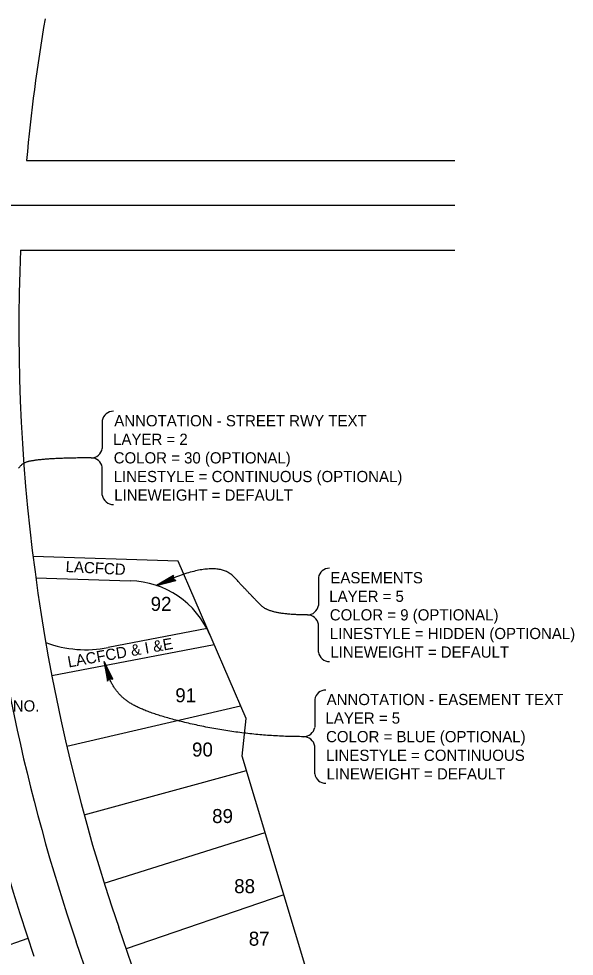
# Model space of a CAD drawing. Extents: x 6387474 to 6390971, y 1972046 to 1973920.
# Drawn here: x 6389581 to 6389978, y 1973251 to 1973920 of the extents above; entities that cross this region are included whole.
import ezdxf

# ---------------------------------------------------------------- set-up
doc = ezdxf.new("R2010")
doc.units = 0
for name, color, linetype in [('1', 7, 'Continuous'), ('2', 7, 'Continuous'), ('3', 7, 'Continuous'), ('4', 7, 'Continuous'), ('5', 7, 'Continuous'), ('7', 7, 'Continuous'), ('8', 7, 'Continuous')]:
    doc.layers.add(name, color=color, linetype=linetype)

msp = doc.modelspace()

# ---------------------------------------------------------------- linework, layer by layer
at = {"layer": '1'}
for p, q in [((6389694.9, 1973533.17), (6389591.38, 1973536.42)), ((6389743.44, 1973420.87), (6389694.9, 1973533.17)), ((6389740.69, 1973394.07), (6389743.44, 1973420.87)), ((6389875.29, 1972944.72), (6389740.69, 1973394.07))]:
    msp.add_line(p, q, dxfattribs=at)
at = {"layer": '2'}
for p, q in [((6389236.57, 1973787.32), (6389892.25, 1973787.32)), ((6389702.59, 1973027.14), (6389622.23, 1973261.52))]:
    msp.add_line(p, q, dxfattribs=at)
msp.add_arc((6390899.27, 1973699.34), 1350, 170.57423, 198.92361, dxfattribs=at)
at = {"layer": '3'}
for p, q in [((6389604.77, 1973451.56), (6389720.59, 1973473.72)), ((6389615.45, 1973401.12), (6389739.52, 1973429.94)), ((6389627.85, 1973352.05), (6389743.79, 1973383.72)), ((6389642.2, 1973303.23), (6389757.06, 1973339.42)), ((6389770.39, 1973294.92), (6389657.84, 1973256.33)), ((6389587.7, 1973263.79), (6389480.83, 1973227.16))]:
    msp.add_line(p, q, dxfattribs=at)
at = {"layer": '4'}
for p, q in [((6389586.74, 1973819.32), (6389892.25, 1973819.32)), ((6389582.46, 1973755.32), (6389892.25, 1973755.32)), ((6389732.86, 1973037.51), (6389652.51, 1973271.9))]:
    msp.add_line(p, q, dxfattribs=at)
for radius, start, end in [(1318, 170.34322, 174.77704), (1382, 177.67854, 198.92361), (1318, 177.56575, 198.92361)]:
    msp.add_arc((6390899.27, 1973699.34), radius, start, end, dxfattribs=at)
at = {"layer": '5'}
for p, q in [((6389593.34, 1973521.35), (6389660.87, 1973519.22)), ((6389715.71, 1973485.01), (6389644.98, 1973471.48))]:
    msp.add_line(p, q, dxfattribs=at)
for centre, radius, start, end in [((6389658.86, 1973455.26), 64, 23.37409, 88.19889), ((6389629.19, 1973553.98), 84, 250.04716, 280.83)]:
    msp.add_arc(centre, radius, start, end, dxfattribs=at)
at = {"layer": '8'}
for p, q in [((6389640.81, 1973633.56), (6389640.81, 1973613.58)), ((6389640.81, 1973580.27), (6389640.81, 1973600.25)), ((6389691.71, 1973523.05), (6389679.56, 1973515.82)), ((6389679.56, 1973515.82), (6389693.25, 1973519.36)), ((6389795.01, 1973521.48), (6389795.01, 1973501.5)), ((6389795.01, 1973468.19), (6389795.01, 1973488.17)), ((6389648.35, 1973448.85), (6389642.16, 1973461.57)), ((6389642.16, 1973461.57), (6389644.54, 1973447.63)), ((6389792.34, 1973434.55), (6389792.34, 1973414.57)), ((6389792.34, 1973381.26), (6389792.34, 1973401.24))]:
    msp.add_line(p, q, dxfattribs=at)
for points in [[(6389632.92, 1973606.91), (6389631.63, 1973606.91), (6389630.37, 1973606.91), (6389629.11, 1973606.9), (6389627.88, 1973606.9), (6389626.66, 1973606.89), (6389625.45, 1973606.88), (6389624.27, 1973606.86), (6389623.1, 1973606.85), (6389621.94, 1973606.83), (6389620.81, 1973606.81), (6389619.68, 1973606.79), (6389618.58, 1973606.77), (6389617.49, 1973606.75), (6389616.42, 1973606.72), (6389615.37, 1973606.69), (6389614.33, 1973606.66), (6389613.31, 1973606.63), (6389612.3, 1973606.6), (6389611.32, 1973606.56), (6389610.35, 1973606.52), (6389609.39, 1973606.48), (6389608.45, 1973606.44), (6389607.53, 1973606.4), (6389606.63, 1973606.35), (6389605.74, 1973606.3), (6389604.86, 1973606.25), (6389604.01, 1973606.2), (6389603.17, 1973606.15), (6389602.35, 1973606.09), (6389601.54, 1973606.04), (6389600.75, 1973605.98), (6389599.98, 1973605.92), (6389599.22, 1973605.85), (6389598.48, 1973605.79), (6389597.76, 1973605.72), (6389597.05, 1973605.65), (6389596.36, 1973605.58), (6389595.69, 1973605.51), (6389595.03, 1973605.43), (6389594.39, 1973605.36), (6389593.77, 1973605.28), (6389593.16, 1973605.2), (6389592.57, 1973605.12), (6389592, 1973605.03), (6389591.44, 1973604.94), (6389590.9, 1973604.86), (6389590.37, 1973604.77), (6389589.87, 1973604.67), (6389589.38, 1973604.58), (6389588.9, 1973604.48), (6389588.44, 1973604.38), (6389588, 1973604.28), (6389587.58, 1973604.18), (6389587.16, 1973604.07), (6389586.76, 1973603.95), (6389586.36, 1973603.81), (6389585.97, 1973603.65), (6389585.59, 1973603.48), (6389585.22, 1973603.3), (6389584.85, 1973603.1), (6389584.49, 1973602.89), (6389584.14, 1973602.66), (6389583.8, 1973602.41), (6389583.47, 1973602.16), (6389583.14, 1973601.88), (6389582.82, 1973601.6), (6389582.51, 1973601.29), (6389582.21, 1973600.98), (6389581.91, 1973600.64), (6389581.63, 1973600.3), (6389581.35, 1973599.94), (6389581.08, 1973599.56)], [(6389737.66, 1973518.77), (6389737.19, 1973519.28), (6389736.71, 1973519.79), (6389736.23, 1973520.3), (6389735.75, 1973520.83), (6389735.26, 1973521.35), (6389734.77, 1973521.88), (6389734.26, 1973522.41), (6389733.74, 1973522.91), (6389733.19, 1973523.38), (6389732.62, 1973523.83), (6389732.04, 1973524.25), (6389731.43, 1973524.65), (6389730.8, 1973525.03), (6389730.15, 1973525.38), (6389729.48, 1973525.71), (6389728.79, 1973526.01), (6389728.08, 1973526.29), (6389727.34, 1973526.54), (6389726.59, 1973526.77), (6389725.82, 1973526.97), (6389725.02, 1973527.15), (6389724.21, 1973527.31), (6389723.37, 1973527.44), (6389722.52, 1973527.55), (6389721.64, 1973527.63), (6389720.74, 1973527.68), (6389719.82, 1973527.72), (6389718.89, 1973527.73), (6389717.93, 1973527.71), (6389716.95, 1973527.67), (6389715.95, 1973527.6), (6389714.92, 1973527.51), (6389713.88, 1973527.4), (6389712.82, 1973527.26), (6389711.74, 1973527.09), (6389710.63, 1973526.91), (6389709.51, 1973526.69), (6389708.37, 1973526.46), (6389707.2, 1973526.2), (6389706.01, 1973525.91), (6389704.81, 1973525.6), (6389703.58, 1973525.26), (6389702.33, 1973524.9), (6389701.06, 1973524.52), (6389699.77, 1973524.11), (6389698.46, 1973523.68), (6389697.13, 1973523.22), (6389695.78, 1973522.74), (6389694.41, 1973522.23), (6389693.02, 1973521.7), (6389691.61, 1973521.14), (6389690.17, 1973520.56), (6389688.72, 1973519.96), (6389687.24, 1973519.33), (6389685.75, 1973518.67), (6389684.23, 1973517.99), (6389682.69, 1973517.29), (6389681.14, 1973516.56), (6389679.56, 1973515.81)], [(6389787.13, 1973494.83), (6389786.15, 1973494.83), (6389785.18, 1973494.84), (6389784.23, 1973494.85), (6389783.3, 1973494.87), (6389782.37, 1973494.89), (6389781.47, 1973494.91), (6389780.57, 1973494.94), (6389779.69, 1973494.98), (6389778.82, 1973495.02), (6389777.97, 1973495.06), (6389777.13, 1973495.11), (6389776.3, 1973495.16), (6389775.49, 1973495.22), (6389774.7, 1973495.28), (6389773.91, 1973495.35), (6389773.14, 1973495.42), (6389772.39, 1973495.49), (6389771.64, 1973495.57), (6389770.92, 1973495.66), (6389770.2, 1973495.75), (6389769.5, 1973495.84), (6389768.82, 1973495.94), (6389768.14, 1973496.04), (6389767.49, 1973496.15), (6389766.84, 1973496.26), (6389766.21, 1973496.38), (6389765.59, 1973496.5), (6389764.99, 1973496.63), (6389764.4, 1973496.76), (6389763.83, 1973496.89), (6389763.27, 1973497.03), (6389762.72, 1973497.18), (6389762.19, 1973497.33), (6389761.67, 1973497.48), (6389761.16, 1973497.64), (6389760.67, 1973497.8), (6389760.19, 1973497.97), (6389759.73, 1973498.14), (6389759.28, 1973498.32), (6389758.85, 1973498.5), (6389758.42, 1973498.68), (6389758.02, 1973498.87), (6389757.62, 1973499.07), (6389757.24, 1973499.27), (6389756.88, 1973499.47), (6389756.53, 1973499.68), (6389756.19, 1973499.89), (6389755.86, 1973500.11), (6389755.55, 1973500.33), (6389755.26, 1973500.56), (6389754.97, 1973500.79), (6389754.71, 1973501.03), (6389754.45, 1973501.27), (6389754.2, 1973501.51), (6389753.95, 1973501.76), (6389753.69, 1973502.02), (6389753.42, 1973502.28), (6389753.16, 1973502.55), (6389752.88, 1973502.82), (6389752.6, 1973503.1), (6389752.32, 1973503.39), (6389752.03, 1973503.68), (6389751.74, 1973503.97), (6389751.45, 1973504.27), (6389751.14, 1973504.58), (6389750.84, 1973504.89), (6389750.53, 1973505.21), (6389750.21, 1973505.53), (6389749.89, 1973505.86), (6389749.57, 1973506.19), (6389749.24, 1973506.53), (6389748.9, 1973506.88), (6389748.57, 1973507.23), (6389748.22, 1973507.58), (6389747.87, 1973507.94), (6389747.52, 1973508.31), (6389747.16, 1973508.68), (6389746.8, 1973509.06), (6389746.44, 1973509.45), (6389746.06, 1973509.83), (6389745.69, 1973510.23), (6389745.31, 1973510.63), (6389744.92, 1973511.03), (6389744.53, 1973511.45), (6389744.14, 1973511.86), (6389743.74, 1973512.28), (6389743.33, 1973512.71), (6389742.93, 1973513.14), (6389742.51, 1973513.58), (6389742.09, 1973514.03), (6389741.67, 1973514.48), (6389741.24, 1973514.93), (6389740.81, 1973515.39), (6389740.37, 1973515.86), (6389739.93, 1973516.33), (6389739.49, 1973516.81), (6389739.04, 1973517.29), (6389738.58, 1973517.78), (6389738.12, 1973518.27), (6389737.66, 1973518.77)], [(6389661.92, 1973431.13), (6389661.34, 1973431.48), (6389660.78, 1973431.82), (6389660.23, 1973432.16), (6389659.7, 1973432.51), (6389659.19, 1973432.85), (6389658.69, 1973433.2), (6389658.21, 1973433.55), (6389657.74, 1973433.91), (6389657.27, 1973434.27), (6389656.81, 1973434.64), (6389656.35, 1973435.02), (6389655.9, 1973435.41), (6389655.46, 1973435.8), (6389655.02, 1973436.2), (6389654.59, 1973436.61), (6389654.17, 1973437.02), (6389653.75, 1973437.45), (6389653.34, 1973437.87), (6389652.94, 1973438.31), (6389652.54, 1973438.75), (6389652.15, 1973439.2), (6389651.77, 1973439.66), (6389651.39, 1973440.12), (6389651.02, 1973440.6), (6389650.66, 1973441.07), (6389650.3, 1973441.56), (6389649.95, 1973442.05), (6389649.6, 1973442.55), (6389649.26, 1973443.06), (6389648.93, 1973443.57), (6389648.61, 1973444.09), (6389648.29, 1973444.62), (6389647.98, 1973445.16), (6389647.67, 1973445.7), (6389647.37, 1973446.25), (6389647.08, 1973446.8), (6389646.79, 1973447.37), (6389646.52, 1973447.94), (6389646.24, 1973448.52), (6389645.98, 1973449.1), (6389645.72, 1973449.69), (6389645.46, 1973450.29), (6389645.22, 1973450.9), (6389644.98, 1973451.51), (6389644.74, 1973452.13), (6389644.52, 1973452.76), (6389644.3, 1973453.4), (6389644.08, 1973454.04), (6389643.88, 1973454.69), (6389643.67, 1973455.34), (6389643.48, 1973456.01), (6389643.29, 1973456.68), (6389643.11, 1973457.35), (6389642.94, 1973458.04), (6389642.77, 1973458.73), (6389642.61, 1973459.43), (6389642.45, 1973460.13), (6389642.3, 1973460.85), (6389642.16, 1973461.57)], [(6389784.45, 1973407.9), (6389783.02, 1973407.9), (6389781.59, 1973407.91), (6389780.17, 1973407.93), (6389778.74, 1973407.95), (6389777.31, 1973407.97), (6389775.89, 1973408), (6389774.46, 1973408.04), (6389773.03, 1973408.08), (6389771.61, 1973408.13), (6389770.18, 1973408.19), (6389768.76, 1973408.25), (6389767.33, 1973408.31), (6389765.9, 1973408.39), (6389764.48, 1973408.46), (6389763.05, 1973408.55), (6389761.63, 1973408.63), (6389760.21, 1973408.73), (6389758.78, 1973408.83), (6389757.36, 1973408.94), (6389755.93, 1973409.05), (6389754.51, 1973409.17), (6389753.09, 1973409.29), (6389751.66, 1973409.42), (6389750.24, 1973409.55), (6389748.82, 1973409.69), (6389747.4, 1973409.84), (6389745.97, 1973409.99), (6389744.55, 1973410.15), (6389743.13, 1973410.31), (6389741.71, 1973410.48), (6389740.29, 1973410.66), (6389738.87, 1973410.84), (6389737.45, 1973411.02), (6389736.03, 1973411.21), (6389734.61, 1973411.41), (6389733.19, 1973411.62), (6389731.77, 1973411.83), (6389730.35, 1973412.04), (6389728.93, 1973412.26), (6389727.51, 1973412.49), (6389726.09, 1973412.72), (6389724.67, 1973412.96), (6389723.25, 1973413.2), (6389721.83, 1973413.45), (6389720.42, 1973413.71), (6389719, 1973413.97), (6389717.58, 1973414.23), (6389716.16, 1973414.51), (6389714.75, 1973414.78), (6389713.33, 1973415.07), (6389711.91, 1973415.36), (6389710.5, 1973415.65), (6389709.08, 1973415.95), (6389707.67, 1973416.26), (6389706.28, 1973416.56), (6389704.91, 1973416.87), (6389703.56, 1973417.18), (6389702.22, 1973417.48), (6389700.9, 1973417.79), (6389699.6, 1973418.1), (6389698.31, 1973418.41), (6389697.05, 1973418.72), (6389695.8, 1973419.03), (6389694.57, 1973419.35), (6389693.35, 1973419.66), (6389692.15, 1973419.97), (6389690.98, 1973420.29), (6389689.81, 1973420.6), (6389688.67, 1973420.92), (6389687.54, 1973421.24), (6389686.44, 1973421.56), (6389685.34, 1973421.87), (6389684.27, 1973422.19), (6389683.21, 1973422.52), (6389682.18, 1973422.84), (6389681.16, 1973423.16), (6389680.15, 1973423.48), (6389679.17, 1973423.81), (6389678.2, 1973424.13), (6389677.25, 1973424.46), (6389676.31, 1973424.78), (6389675.4, 1973425.11), (6389674.5, 1973425.44), (6389673.62, 1973425.77), (6389672.76, 1973426.09), (6389671.91, 1973426.42), (6389671.08, 1973426.76), (6389670.27, 1973427.09), (6389669.48, 1973427.42), (6389668.71, 1973427.75), (6389667.95, 1973428.09), (6389667.21, 1973428.42), (6389666.49, 1973428.76), (6389665.78, 1973429.1), (6389665.1, 1973429.43), (6389664.43, 1973429.77), (6389663.77, 1973430.11), (6389663.14, 1973430.45), (6389662.52, 1973430.79), (6389661.92, 1973431.13)]]:
    msp.add_lwpolyline(points, dxfattribs=at)
for points in [[(6389679.56, 1973515.82), (6389691.48, 1973522.53), (6389691.71, 1973523.05)], [(6389679.56, 1973515.82), (6389691.37, 1973521.96), (6389691.48, 1973522.53)], [(6389679.56, 1973515.82), (6389691.4, 1973521.38), (6389691.37, 1973521.96)], [(6389691.56, 1973520.82), (6389691.4, 1973521.38), (6389679.56, 1973515.82)], [(6389691.84, 1973520.32), (6389691.56, 1973520.82), (6389679.56, 1973515.82)], [(6389692.23, 1973519.89), (6389691.84, 1973520.32), (6389679.56, 1973515.82)], [(6389692.71, 1973519.57), (6389692.23, 1973519.89), (6389679.56, 1973515.82)], [(6389693.25, 1973519.36), (6389692.71, 1973519.57), (6389679.56, 1973515.82)], [(6389642.16, 1973461.57), (6389646.7, 1973449.3), (6389647.28, 1973449.28)], [(6389642.16, 1973461.57), (6389647.28, 1973449.28), (6389647.84, 1973449.13)], [(6389642.16, 1973461.57), (6389647.84, 1973449.13), (6389648.35, 1973448.85)], [(6389646.14, 1973449.19), (6389646.7, 1973449.3), (6389642.16, 1973461.57)], [(6389645.61, 1973448.95), (6389646.14, 1973449.19), (6389642.16, 1973461.57)], [(6389645.15, 1973448.6), (6389645.61, 1973448.95), (6389642.16, 1973461.57)], [(6389644.79, 1973448.15), (6389645.15, 1973448.6), (6389642.16, 1973461.57)], [(6389644.54, 1973447.63), (6389644.79, 1973448.15), (6389642.16, 1973461.57)]]:
    msp.add_lwpolyline(points, close=True, dxfattribs=at)
for centre, radius, start, end in [((6389648.7, 1973632.22), 8, 90, 170.38048), ((6389632.92, 1973614.91), 8, 270, 350.38048), ((6389632.92, 1973598.91), 8, 9.61952, 90), ((6389648.7, 1973581.61), 8, 189.61952, 270), ((6389802.9, 1973520.14), 8, 90, 170.38048), ((6389693.86, 1973521.79), 2.5, 149.5258, 255.78601), ((6389787.13, 1973502.83), 8, 270, 350.38048), ((6389787.13, 1973486.83), 8, 9.61952, 90), ((6389802.9, 1973469.53), 8, 189.61952, 270), ((6389646.9, 1973446.81), 2.5, 54.67709, 160.9373), ((6389800.23, 1973433.21), 8, 90, 170.38048), ((6389784.45, 1973415.9), 8, 270, 350.38048), ((6389784.45, 1973399.9), 8, 9.61952, 90), ((6389800.23, 1973382.6), 8, 189.61952, 270)]:
    msp.add_arc(centre, radius, start, end, dxfattribs=at)

# ---------------------------------------------------------------- texts
at = {"layer": '5'}
for s, rotation, p in [('LACFCD', 357.0079, (6389614.49, 1973525.48)), ('LACFCD & I &E', 10.17001, (6389616.8, 1973457.23))]:
    msp.add_text(s, height=8, rotation=rotation, dxfattribs=at).set_placement(p)
at = {"layer": '7'}
for s, p in [('92', (6389675.27, 1973497.71)), ('91', (6389692.88, 1973432.45)), ('90', (6389704.82, 1973393.72)), ('89', (6389719.18, 1973346.25)), ('88', (6389734.91, 1973296.15)), ('87', (6389745.3, 1973258.68))]:
    msp.add_text(s, height=10, dxfattribs=at).set_placement(p)
at = {"layer": '8'}
for s, p in [('ANNOTATION - STREET RWY TEXT', (6389649.34, 1973629.46)), ('LAYER = 2', (6389648.53, 1973616.21)), ('COLOR = 30 (OPTIONAL)', (6389648.92, 1973602.95)), ('LINESTYLE = CONTINUOUS (OPTIONAL)', (6389648.92, 1973589.63)), ('LINEWEIGHT = DEFAULT', (6389649.31, 1973576.37)), ('EASEMENTS', (6389803.55, 1973517.38)), ('LAYER = 5', (6389802.74, 1973504.13)), ('COLOR = 9 (OPTIONAL)', (6389803.13, 1973490.87)), ('LINESTYLE = HIDDEN (OPTIONAL)', (6389803.13, 1973477.55)), ('LINEWEIGHT = DEFAULT', (6389803.52, 1973464.29)), ('ANNOTATION - EASEMENT TEXT', (6389800.87, 1973430.44)), ('ANNOTATION - LOT & PARCEL NO.', (6389417.61, 1973425.87)), ('LAYER = 5', (6389800.06, 1973417.2)), ('COLOR = BLUE (OPTIONAL)', (6389800.45, 1973403.94)), ('LINESTYLE = CONTINUOUS', (6389800.45, 1973390.62)), ('LINEWEIGHT = DEFAULT', (6389800.84, 1973377.36))]:
    msp.add_text(s, height=8, dxfattribs=at).set_placement(p)

doc.saveas('drawing.dxf')
